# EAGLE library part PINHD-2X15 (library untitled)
PIN HEADER
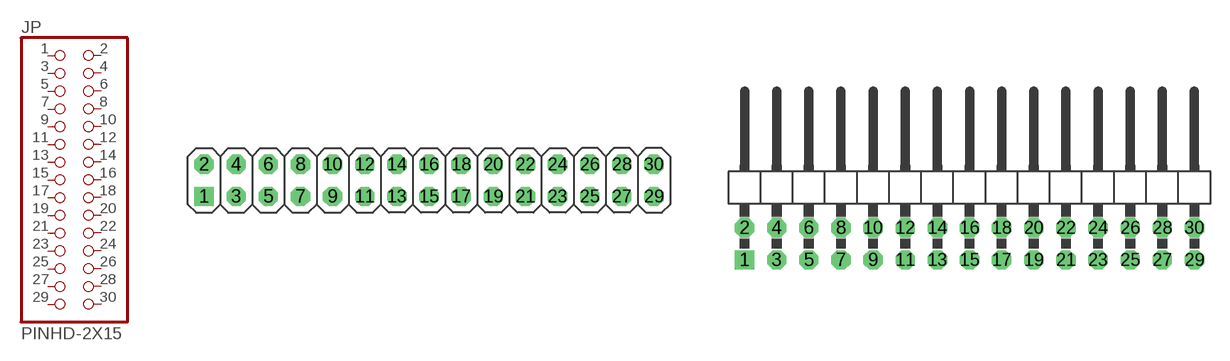
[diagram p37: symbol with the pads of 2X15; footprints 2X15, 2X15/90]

Designator prefix JP

## PINHD-2X15_2.54  [2X15]
1  1  pas
2  2  pas
3  3  pas
4  4  pas
5  5  pas
6  6  pas
7  7  pas
8  8  pas
9  9  pas
10  10  pas
11  11  pas
12  12  pas
13  13  pas
14  14  pas
15  15  pas
16  16  pas
17  17  pas
18  18  pas
19  19  pas
20  20  pas
21  21  pas
22  22  pas
23  23  pas
24  24  pas
25  25  pas
26  26  pas
27  27  pas
28  28  pas
29  29  pas
30  30  pas

## PINHD-2X15_2.54-90°  [2X15/90]
Pads as for 2X15

## PINHD-2X15_2.00  [2X15M]
Pads as for 2X15

## PINHD-2X15_2.54-SMD  [2X15SMD]
Pads as for 2X15

## PINHD-2X15_2.54-SMD-90°  [2X15SMD/90]
Pads as for 2X15

## Footprint 2X15 (pad centres in mm)
PIN HEADER - 2.54
drill 1.016 square: 1 -17.78,-1.27
drill 1.016 octagon: 2 -17.78,1.27; 3 -15.24,-1.27; 4 -15.24,1.27; 5 -12.7,-1.27; 6 -12.7,1.27; 7 -10.16,-1.27; 8 -10.16,1.27; 9 -7.62,-1.27; 10 -7.62,1.27; 11 -5.08,-1.27; 12 -5.08,1.27; 13 -2.54,-1.27; 14 -2.54,1.27; 15 0,-1.27; 16 0,1.27; 17 2.54,-1.27; 18 2.54,1.27; 19 5.08,-1.27; 20 5.08,1.27; 21 7.62,-1.27; 22 7.62,1.27; 23 10.16,-1.27; 24 10.16,1.27; 25 12.7,-1.27; 26 12.7,1.27; 27 15.24,-1.27; 28 15.24,1.27; 29 17.78,-1.27; 30 17.78,1.27

## Footprint 2X15/90 (pad centres in mm)
PIN HEADER - 2.54 90°
drill 1.016 square: 1 -17.78,-6.35
drill 1.016 octagon: 2 -17.78,-3.81; 3 -15.24,-6.35; 4 -15.24,-3.81; 5 -12.7,-6.35; 6 -12.7,-3.81; 7 -10.16,-6.35; 8 -10.16,-3.81; 9 -7.62,-6.35; 10 -7.62,-3.81; 11 -5.08,-6.35; 12 -5.08,-3.81; 13 -2.54,-6.35; 14 -2.54,-3.81; 15 0,-6.35; 16 0,-3.81; 17 2.54,-6.35; 18 2.54,-3.81; 19 5.08,-6.35; 20 5.08,-3.81; 21 7.62,-6.35; 22 7.62,-3.81; 23 10.16,-6.35; 24 10.16,-3.81; 25 12.7,-6.35; 26 12.7,-3.81; 27 15.24,-6.35; 28 15.24,-3.81; 29 17.78,-6.35; 30 17.78,-3.81

## Footprint 2X15M (pad centres in mm)
PIN HEADER - 2
drill 0.914 square: 1 -14,-1
drill 0.914 round: 2 -14,1; 3 -12,-1; 4 -12,1; 5 -10,-1; 6 -10,1; 7 -8,-1; 8 -8,1; 9 -6,-1; 10 -6,1; 11 -4,-1; 12 -4,1; 13 -2,-1; 14 -2,1; 15 0,-1; 16 0,1; 17 2,-1; 18 2,1; 19 4,-1; 20 4,1; 21 6,-1; 22 6,1; 23 8,-1; 24 8,1; 25 10,-1; 26 10,1; 27 12,-1; 28 12,1; 29 14,-1; 30 14,1

## Footprint 2X15SMD (pad centres in mm)
PIN HEADER - 2.54 SMD
smd 1.016 x 3.302: 1 -1.27,-3.81; 2 -1.27,1.27; 3 1.27,-3.81; 4 1.27,1.27; 5 3.81,-3.81; 6 3.81,1.27; 7 6.35,-3.81; 8 6.35,1.27; 9 8.89,-3.81; 10 8.89,1.27; 11 11.43,-3.81; 12 11.43,1.27; 13 13.97,-3.81; 14 13.97,1.27; 15 16.51,-3.81; 16 16.51,1.27; 17 19.05,-3.81; 18 19.05,1.27; 19 21.59,-3.81; 20 21.59,1.27; 21 24.13,-3.81; 22 24.13,1.27; 23 26.67,-3.81; 24 26.67,1.27; 25 29.21,-3.81; 26 29.21,1.27; 27 31.75,-3.81; 28 31.75,1.27; 29 34.29,-3.81; 30 34.29,1.27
